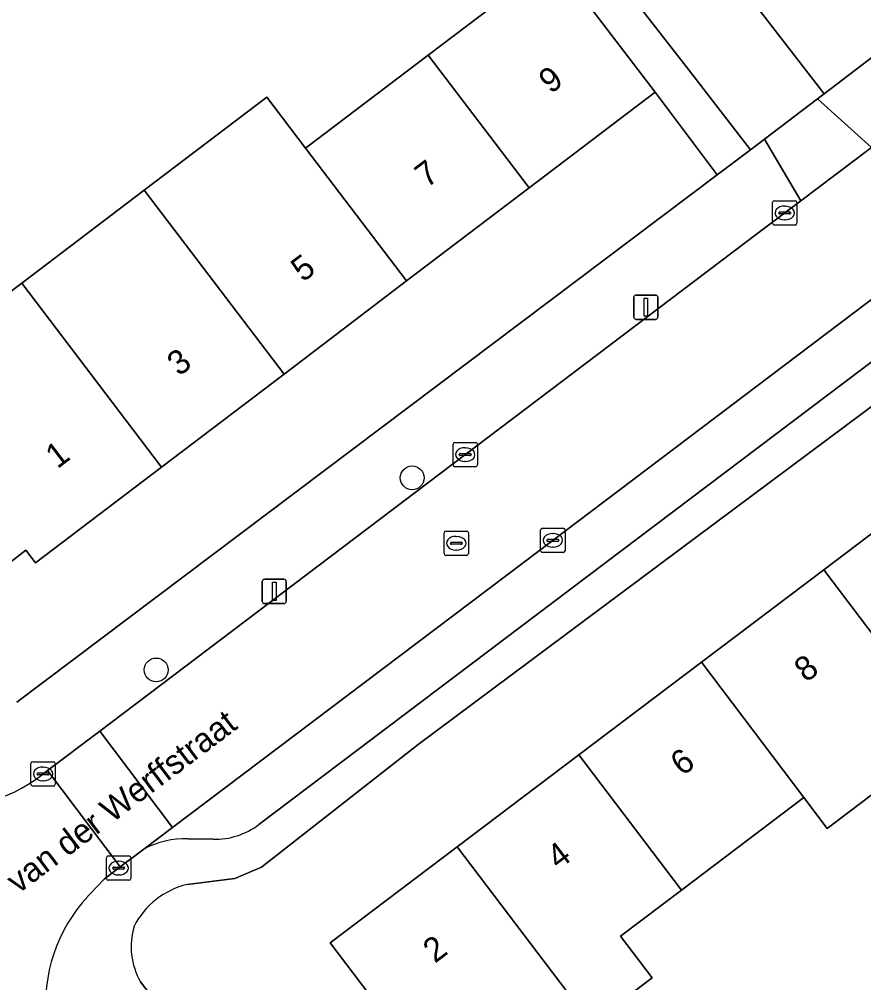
# Model space of a CAD drawing. Extents: x 160030 to 160839, y 385325 to 386450.
# Drawn here: x 160405.72 to 160440.44, y 385842.6 to 385882.22 of the extents above; entities that cross this region are included whole.
import ezdxf

# ---------------------------------------------------------------- set-up
doc = ezdxf.new("R2010")
doc.units = 0
for name, color, linetype in [('IMGEO_Boom', 7, 'Continuous'), ('IMGEO_Erf', 7, 'Continuous'), ('IMGEO_Kolk', 7, 'Continuous'), ('IMGEO_Lichtmast', 7, 'Continuous'), ('IMGEO_Openbare_ruimte_label', 7, 'Continuous'), ('IMGEO_Pand', 7, 'Continuous'), ('IMGEO_Pand_nummerreeks', 7, 'Continuous'), ('IMGEO_Parkeervlak_open', 7, 'Continuous'), ('IMGEO_Rijbaan_lokaal_open', 7, 'Continuous'), ('IMGEO_Rioolput', 7, 'Continuous'), ('IMGEO_Voetpad_open', 7, 'Continuous')]:
    doc.layers.add(name, color=color, linetype=linetype)

msp = doc.modelspace()

# ---------------------------------------------------------------- linework, layer by layer
at = {"layer": 'IMGEO_Boom'}
for centre in [(160421.874, 385863.359), (160411.348, 385855.461)]:
    msp.add_circle(centre, 0.489, dxfattribs=at)
at = {"layer": 'IMGEO_Erf'}
for points in [[(160420.415, 385933.281), (160423.895, 385928.01), (160427.375, 385922.74), (160430.855, 385917.469), (160434.335, 385912.199), (160437.816, 385906.927), (160441.295, 385901.657), (160444.694, 385896.509), (160444.776, 385896.386), (160446.359, 385893.988), (160447.234, 385894.566), (160447.346, 385894.286), (160449.936, 385890.337), (160446.568, 385888.118), (160445.867, 385889.187), (160441.475, 385886.287), (160439.601, 385889.125), (160434.092, 385885.242), (160436.233, 385882.478), (160438.808, 385879.155), (160450.853, 385888.364)], [(160415.895, 385879.021), (160417.494, 385876.916), (160422.532, 385880.746), (160427.708, 385884.68)], [(160405.621, 385854.135), (160434.418, 385875.821), (160431.858, 385879.22), (160426.682, 385875.285), (160421.644, 385871.456), (160416.605, 385867.626), (160411.568, 385863.797), (160406.392, 385859.863), (160405.996, 385860.384), (160404.814, 385859.485), (160403.13, 385861.701), (160404.306, 385862.595), (160402.235, 385865.319), (160400.625, 385867.441), (160405.82, 385871.362), (160410.857, 385875.191), (160415.895, 385879.021)], [(160438.794, 385859.583), (160443.827, 385863.39), (160449.02, 385867.319), (160450.696, 385865.104), (160452.838, 385866.725), (160448.695, 385872.214), (160446.573, 385870.631), (160422.124, 385852.4), (160415.683, 385847.347), (160414.577, 385846.885), (160412.621, 385846.639)], [(160410.71, 385842.631), (160424.459, 385824.597), (160430.089, 385828.889), (160428.548, 385830.926), (160426.66, 385833.421), (160428.183, 385834.573), (160424.807, 385839.037), (160422.223, 385837.082), (160419.315, 385840.926), (160420.391, 385841.74), (160418.504, 385844.234), (160423.728, 385848.186), (160428.73, 385851.97), (160433.762, 385855.777), (160438.794, 385859.583)], [(160443.965, 385852.747), (160438.934, 385848.941), (160437.974, 385850.21), (160432.942, 385846.403), (160430.444, 385844.513), (160431.738, 385842.801), (160429.235, 385840.908), (160431.9, 385837.385), (160432.944, 385836.044), (160437.184, 385839.347), (160439.577, 385836.275), (160442.546, 385838.653)]]:
    msp.add_lwpolyline(points, dxfattribs=at)
for centre, radius, start, end in [((160413.395, 385843.416), 3.315, 103.5014, 152.9338), ((160413.213, 385844.085), 2.895, 163.142, 210.1414)]:
    msp.add_arc(centre, radius, start, end, dxfattribs=at)
at = {"layer": 'IMGEO_Kolk'}
for p, q in [((160436.765, 385874.755), (160437.617, 385874.755)), ((160436.69, 385873.829), (160436.69, 385874.681)), ((160436.992, 385874.298), (160437.39, 385874.298)), ((160437.178, 385874.535), (160437.203, 385874.535)), ((160437.691, 385874.681), (160437.691, 385873.829)), ((160436.949, 385874.249), (160436.949, 385874.261)), ((160437.387, 385874.212), (160436.989, 385874.212)), ((160437.201, 385873.975), (160437.176, 385873.975)), ((160437.433, 385874.261), (160437.433, 385874.249)), ((160437.617, 385873.755), (160436.765, 385873.755)), ((160423.627, 385864.818), (160424.479, 385864.818)), ((160423.552, 385863.892), (160423.552, 385864.744)), ((160424.04, 385864.598), (160424.065, 385864.598)), ((160424.553, 385864.744), (160424.553, 385863.892)), ((160423.811, 385864.312), (160423.811, 385864.324)), ((160424.249, 385864.275), (160423.851, 385864.275)), ((160423.854, 385864.361), (160424.252, 385864.361)), ((160424.063, 385864.038), (160424.038, 385864.038)), ((160424.295, 385864.324), (160424.295, 385864.312)), ((160424.479, 385863.818), (160423.627, 385863.818)), ((160427.155, 385860.364), (160427.155, 385861.216)), ((160427.23, 385861.29), (160428.082, 385861.29)), ((160428.156, 385861.216), (160428.156, 385860.364)), ((160427.457, 385860.833), (160427.855, 385860.833)), ((160427.643, 385861.07), (160427.668, 385861.07)), ((160427.414, 385860.784), (160427.414, 385860.796)), ((160427.852, 385860.747), (160427.454, 385860.747)), ((160427.666, 385860.51), (160427.641, 385860.51)), ((160427.898, 385860.796), (160427.898, 385860.784)), ((160428.082, 385860.29), (160427.23, 385860.29)), ((160406.2, 385850.76), (160406.2, 385851.612)), ((160406.275, 385851.686), (160407.127, 385851.686)), ((160406.688, 385851.466), (160406.713, 385851.466)), ((160407.201, 385851.612), (160407.201, 385850.76)), ((160406.459, 385851.18), (160406.459, 385851.192)), ((160406.897, 385851.143), (160406.499, 385851.143)), ((160406.502, 385851.229), (160406.9, 385851.229)), ((160406.943, 385851.192), (160406.943, 385851.18)), ((160407.127, 385850.686), (160406.275, 385850.686)), ((160406.711, 385850.906), (160406.686, 385850.906)), ((160409.378, 385847.812), (160410.23, 385847.812)), ((160409.303, 385846.886), (160409.303, 385847.738)), ((160409.605, 385847.355), (160410.003, 385847.355)), ((160409.791, 385847.592), (160409.816, 385847.592)), ((160410.304, 385847.738), (160410.304, 385846.886)), ((160409.562, 385847.306), (160409.562, 385847.318)), ((160410, 385847.269), (160409.602, 385847.269)), ((160409.814, 385847.032), (160409.789, 385847.032)), ((160410.046, 385847.318), (160410.046, 385847.306)), ((160410.23, 385846.812), (160409.378, 385846.812))]:
    msp.add_line(p, q, dxfattribs=at)
for points in [[(160436.765, 385874.755), (160437.617, 385874.755)], [(160436.69, 385873.829), (160436.69, 385874.681)], [(160437.691, 385874.681), (160437.691, 385873.829)], [(160437.617, 385873.755), (160436.765, 385873.755)], [(160423.627, 385864.818), (160424.479, 385864.818)], [(160423.552, 385863.892), (160423.552, 385864.744)], [(160424.553, 385864.744), (160424.553, 385863.892)], [(160424.479, 385863.818), (160423.627, 385863.818)], [(160427.155, 385860.364), (160427.155, 385861.216)], [(160427.23, 385861.29), (160428.082, 385861.29)], [(160428.156, 385861.216), (160428.156, 385860.364)], [(160428.082, 385860.29), (160427.23, 385860.29)], [(160406.2, 385850.76), (160406.2, 385851.612)], [(160406.275, 385851.686), (160407.127, 385851.686)], [(160407.201, 385851.612), (160407.201, 385850.76)], [(160407.127, 385850.686), (160406.275, 385850.686)], [(160409.378, 385847.812), (160410.23, 385847.812)], [(160409.303, 385846.886), (160409.303, 385847.738)], [(160410.304, 385847.738), (160410.304, 385846.886)], [(160410.23, 385846.812), (160409.378, 385846.812)]]:
    msp.add_lwpolyline(points, dxfattribs=at)
for centre, radius, start, end in [((160436.767, 385874.679), 0.0765, 91.552, 178.448), ((160436.767, 385874.679), 0.0765, 91.552, 178.448), ((160437.615, 385874.679), 0.0765, 1.552, 88.448), ((160437.615, 385874.679), 0.0765, 1.552, 88.448), ((160436.989, 385874.258), 0.0403, 85.8775, 175.7526), ((160437.394, 385874.26), 0.0386, 1.7309, 96.639), ((160436.986, 385874.248), 0.0366, 178.938, 274.7102), ((160437.39, 385874.255), 0.043, 264.8664, 352.4533), ((160436.767, 385873.831), 0.0765, 181.552, 268.448), ((160436.767, 385873.831), 0.0765, 181.552, 268.448), ((160437.615, 385873.831), 0.0765, 271.552, 358.448), ((160437.615, 385873.831), 0.0765, 271.552, 358.448), ((160423.629, 385864.742), 0.0765, 91.552, 178.448), ((160423.629, 385864.742), 0.0765, 91.552, 178.448), ((160424.477, 385864.742), 0.0765, 1.552, 88.448), ((160424.477, 385864.742), 0.0765, 1.552, 88.448), ((160423.851, 385864.321), 0.0403, 85.8775, 175.7526), ((160423.848, 385864.311), 0.0366, 178.938, 274.7102), ((160424.252, 385864.318), 0.043, 264.8664, 352.4533), ((160424.256, 385864.323), 0.0386, 1.7309, 96.639), ((160423.629, 385863.894), 0.0765, 181.552, 268.448), ((160423.629, 385863.894), 0.0765, 181.552, 268.448), ((160424.477, 385863.894), 0.0765, 271.552, 358.448), ((160424.477, 385863.894), 0.0765, 271.552, 358.448), ((160427.232, 385861.214), 0.0765, 91.552, 178.448), ((160427.232, 385861.214), 0.0765, 91.552, 178.448), ((160428.08, 385861.214), 0.0765, 1.552, 88.448), ((160428.08, 385861.214), 0.0765, 1.552, 88.448), ((160427.454, 385860.793), 0.0403, 85.8775, 175.7526), ((160427.859, 385860.795), 0.0386, 1.7309, 96.639), ((160427.451, 385860.783), 0.0366, 178.938, 274.7102), ((160427.855, 385860.79), 0.043, 264.8664, 352.4533), ((160427.232, 385860.366), 0.0765, 181.552, 268.448), ((160427.232, 385860.366), 0.0765, 181.552, 268.448), ((160428.08, 385860.366), 0.0765, 271.552, 358.448), ((160428.08, 385860.366), 0.0765, 271.552, 358.448), ((160406.277, 385851.61), 0.0765, 91.552, 178.448), ((160406.277, 385851.61), 0.0765, 91.552, 178.448), ((160407.125, 385851.61), 0.0765, 1.552, 88.448), ((160407.125, 385851.61), 0.0765, 1.552, 88.448), ((160406.499, 385851.189), 0.0403, 85.8775, 175.7526), ((160406.496, 385851.179), 0.0366, 178.938, 274.7102), ((160406.9, 385851.186), 0.043, 264.8664, 352.4533), ((160406.904, 385851.191), 0.0386, 1.7309, 96.639), ((160406.277, 385850.762), 0.0765, 181.552, 268.448), ((160406.277, 385850.762), 0.0765, 181.552, 268.448), ((160407.125, 385850.762), 0.0765, 271.552, 358.448), ((160407.125, 385850.762), 0.0765, 271.552, 358.448), ((160409.38, 385847.736), 0.0765, 91.552, 178.448), ((160409.38, 385847.736), 0.0765, 91.552, 178.448), ((160410.228, 385847.736), 0.0765, 1.552, 88.448), ((160410.228, 385847.736), 0.0765, 1.552, 88.448), ((160409.602, 385847.315), 0.0403, 85.8775, 175.7526), ((160410.007, 385847.317), 0.0386, 1.7309, 96.639), ((160409.599, 385847.305), 0.0366, 178.938, 274.7102), ((160410.003, 385847.312), 0.043, 264.8664, 352.4533), ((160409.38, 385846.888), 0.0765, 181.552, 268.448), ((160409.38, 385846.888), 0.0765, 181.552, 268.448), ((160410.228, 385846.888), 0.0765, 271.552, 358.448), ((160410.228, 385846.888), 0.0765, 271.552, 358.448)]:
    msp.add_arc(centre, radius, start, end, dxfattribs=at)
for centre, major_axis, ratio, start_param, end_param in [((160437.177, 385874.255), (-0.387, 0.002), 0.722429, 4.712389, 7.853982), ((160437.202, 385874.255), (-0.39, 0.002), 0.717154, 1.570796, 4.712389), ((160424.039, 385864.318), (-0.387, 0.002), 0.722429, 4.712389, 7.853982), ((160424.064, 385864.318), (-0.39, 0.002), 0.717154, 1.570796, 4.712389), ((160427.642, 385860.79), (-0.387, 0.002), 0.722429, 4.712389, 7.853982), ((160427.667, 385860.79), (-0.39, 0.002), 0.717154, 1.570796, 4.712389), ((160406.687, 385851.186), (-0.387, 0.002), 0.722429, 4.712389, 7.853982), ((160406.712, 385851.186), (-0.39, 0.002), 0.717154, 1.570796, 4.712389), ((160409.79, 385847.312), (-0.387, 0.002), 0.722429, 4.712389, 7.853982), ((160409.815, 385847.312), (-0.39, 0.002), 0.717154, 1.570796, 4.712389)]:
    msp.add_ellipse(centre, major_axis=major_axis, ratio=ratio, start_param=start_param, end_param=end_param, dxfattribs=at)
at = {"layer": 'IMGEO_Lichtmast'}
for p, q in [((160430.984, 385869.978), (160430.984, 385870.778)), ((160430.984, 385870.778), (160430.984, 385869.978)), ((160431.084, 385870.878), (160431.874, 385870.878)), ((160431.874, 385870.878), (160431.084, 385870.878)), ((160431.974, 385870.778), (160431.974, 385869.978)), ((160431.974, 385869.978), (160431.974, 385870.778)), ((160431.874, 385869.878), (160431.084, 385869.878)), ((160431.084, 385869.878), (160431.874, 385869.878)), ((160415.705, 385858.292), (160415.705, 385859.092)), ((160415.705, 385859.092), (160415.705, 385858.292)), ((160415.805, 385859.192), (160416.595, 385859.192)), ((160416.595, 385859.192), (160415.805, 385859.192)), ((160416.695, 385859.092), (160416.695, 385858.292)), ((160416.695, 385858.292), (160416.695, 385859.092)), ((160416.595, 385858.192), (160415.805, 385858.192)), ((160415.805, 385858.192), (160416.595, 385858.192))]:
    msp.add_line(p, q, dxfattribs=at)
for points in [[(160431.404, 385870.753), (160431.554, 385870.753), (160431.554, 385870.003), (160431.404, 385870.003), (160431.404, 385870.753)], [(160416.125, 385859.067), (160416.275, 385859.067), (160416.275, 385858.317), (160416.125, 385858.317), (160416.125, 385859.067)]]:
    msp.add_lwpolyline(points, dxfattribs=at)
for centre, start, end in [((160431.084, 385870.778), 90, 180), ((160431.084, 385870.778), 90, 180), ((160431.874, 385870.778), 0, 90), ((160431.874, 385870.778), 360, 90), ((160431.084, 385869.978), 180, 270), ((160431.084, 385869.978), 180, 270), ((160431.874, 385869.978), 270, 0), ((160431.874, 385869.978), 270, 0), ((160415.805, 385859.092), 90, 180), ((160415.805, 385859.092), 90, 180), ((160416.595, 385859.092), 0, 90), ((160416.595, 385859.092), 360, 90), ((160415.805, 385858.292), 180, 270), ((160415.805, 385858.292), 180, 270), ((160416.595, 385858.292), 270, 0), ((160416.595, 385858.292), 270, 0)]:
    msp.add_arc(centre, 0.1, start, end, dxfattribs=at)
at = {"layer": 'IMGEO_Pand'}
for points in [[(160447.346, 385894.286), (160447.234, 385894.566), (160446.359, 385893.988), (160444.776, 385896.386), (160436.026, 385890.609), (160436.235, 385890.293), (160429.208, 385885.34), (160433.229, 385880.15), (160435.785, 385876.851), (160436.363, 385877.291), (160438.538, 385878.95), (160438.808, 385879.155), (160436.233, 385882.478), (160434.092, 385885.242), (160439.601, 385889.125), (160441.475, 385886.287), (160445.867, 385889.187), (160446.568, 385888.118), (160449.936, 385890.337)], [(160426.682, 385875.285), (160431.858, 385879.22), (160428.832, 385883.201), (160427.708, 385884.68), (160422.532, 385880.746)], [(160421.644, 385871.456), (160426.682, 385875.285), (160422.532, 385880.746), (160417.494, 385876.916)], [(160415.895, 385879.021), (160410.857, 385875.191), (160416.605, 385867.626), (160421.644, 385871.456), (160417.494, 385876.916)], [(160405.82, 385871.362), (160411.568, 385863.797), (160416.605, 385867.626), (160410.857, 385875.191)], [(160404.306, 385862.595), (160403.13, 385861.701), (160404.814, 385859.485), (160405.996, 385860.384), (160406.392, 385859.863), (160411.568, 385863.797), (160405.82, 385871.362), (160400.625, 385867.441), (160402.235, 385865.319)], [(160443.965, 385852.747), (160448.998, 385856.554), (160443.827, 385863.39), (160438.794, 385859.583)], [(160438.794, 385859.583), (160433.762, 385855.777), (160437.974, 385850.21), (160438.934, 385848.941), (160443.965, 385852.747)], [(160432.942, 385846.403), (160437.974, 385850.21), (160433.762, 385855.777), (160428.73, 385851.97)], [(160428.73, 385851.97), (160423.728, 385848.186), (160427.94, 385842.619), (160429.235, 385840.908), (160431.738, 385842.801), (160430.444, 385844.513), (160432.942, 385846.403)], [(160423.728, 385848.186), (160418.504, 385844.234), (160420.391, 385841.74), (160419.315, 385840.926), (160422.223, 385837.082), (160424.807, 385839.037), (160428.183, 385834.573), (160431.9, 385837.385), (160429.235, 385840.908), (160427.94, 385842.619)]]:
    msp.add_lwpolyline(points, close=True, dxfattribs=at)
at = {"layer": 'IMGEO_Parkeervlak_open'}
for points in [[(160447.076, 385875.542), (160443.404, 385872.69), (160426.43, 385859.865), (160412.023, 385848.989), (160410.839, 385848.095)], [(160415.566, 385849.104), (160427.661, 385858.235), (160444.594, 385871.028)], [(160412.663, 385848.523), (160413.69, 385848.499)]]:
    msp.add_lwpolyline(points, dxfattribs=at)
for centre, radius, start, end in [((160413.758, 385851.498), 3, 268.6962, 307.0523), ((160412.597, 385844.705), 3.818, 89.0031, 117.4079)]:
    msp.add_arc(centre, radius, start, end, dxfattribs=at)
at = {"layer": 'IMGEO_Rijbaan_lokaal_open'}
for points in [[(160443.404, 385872.69), (160447.076, 385875.542), (160449.202, 385877.266), (160452.197, 385879.558), (160453.06, 385880.219), (160450.2, 385884.038), (160440.762, 385876.939), (160437.848, 385874.748), (160436.031, 385873.381), (160409.033, 385852.95), (160412.023, 385848.989), (160426.43, 385859.865)], [(160409.868, 385847.362), (160410.839, 385848.095), (160412.023, 385848.989), (160409.033, 385852.95), (160406.88, 385851.321)]]:
    msp.add_lwpolyline(points, close=True, dxfattribs=at)
msp.add_lwpolyline([(160408.532, 385846.148), (160408.633, 385846.261), (160409.205, 385846.861), (160409.868, 385847.362), (160406.88, 385851.321), (160406.582, 385851.095)], dxfattribs=at)
for centre, radius, start, end in [((160402.795, 385856.104), 6.279, 262.3776, 307.0912), ((160413.391, 385841.69), 6.594, 137.4643, 185.4835)]:
    msp.add_arc(centre, radius, start, end, dxfattribs=at)
at = {"layer": 'IMGEO_Rioolput'}
for p, q in [((160423.184, 385860.246), (160423.184, 385861.098)), ((160423.259, 385861.172), (160424.111, 385861.172)), ((160423.672, 385860.952), (160423.697, 385860.952)), ((160424.185, 385861.098), (160424.185, 385860.246)), ((160423.443, 385860.666), (160423.443, 385860.678)), ((160423.881, 385860.629), (160423.483, 385860.629)), ((160423.486, 385860.715), (160423.884, 385860.715)), ((160423.927, 385860.678), (160423.927, 385860.666)), ((160424.111, 385860.172), (160423.259, 385860.172)), ((160423.695, 385860.392), (160423.67, 385860.392))]:
    msp.add_line(p, q, dxfattribs=at)
for points in [[(160423.184, 385860.246), (160423.184, 385861.098)], [(160423.259, 385861.172), (160424.111, 385861.172)], [(160424.185, 385861.098), (160424.185, 385860.246)], [(160424.111, 385860.172), (160423.259, 385860.172)]]:
    msp.add_lwpolyline(points, dxfattribs=at)
for centre, radius, start, end in [((160423.261, 385861.096), 0.0765, 91.552, 178.448), ((160423.261, 385861.096), 0.0765, 91.552, 178.448), ((160424.109, 385861.096), 0.0765, 1.552, 88.448), ((160424.109, 385861.096), 0.0765, 1.552, 88.448), ((160423.483, 385860.675), 0.0403, 85.8775, 175.7526), ((160423.48, 385860.665), 0.0366, 178.938, 274.7102), ((160423.884, 385860.672), 0.043, 264.8664, 352.4533), ((160423.888, 385860.677), 0.0386, 1.7309, 96.639), ((160423.261, 385860.248), 0.0765, 181.552, 268.448), ((160423.261, 385860.248), 0.0765, 181.552, 268.448), ((160424.109, 385860.248), 0.0765, 271.552, 358.448), ((160424.109, 385860.248), 0.0765, 271.552, 358.448)]:
    msp.add_arc(centre, radius, start, end, dxfattribs=at)
for centre, major_axis, ratio, start_param, end_param in [((160423.671, 385860.672), (-0.387, 0.002), 0.722429, 4.712389, 7.853982), ((160423.696, 385860.672), (-0.39, 0.002), 0.717154, 1.570796, 4.712389)]:
    msp.add_ellipse(centre, major_axis=major_axis, ratio=ratio, start_param=start_param, end_param=end_param, dxfattribs=at)
at = {"layer": 'IMGEO_Voetpad_open'}
for points in [[(160450.853, 385888.364), (160438.808, 385879.155), (160438.538, 385878.95), (160440.762, 385876.939), (160450.2, 385884.038), (160450.387, 385884.179), (160452.524, 385885.786), (160452.649, 385885.88), (160453.978, 385886.975)], [(160428.832, 385883.201), (160431.858, 385879.22), (160434.418, 385875.821), (160435.785, 385876.851), (160433.229, 385880.15), (160429.208, 385885.34)], [(160436.031, 385873.381), (160437.848, 385874.748), (160436.363, 385877.291), (160435.785, 385876.851), (160434.418, 385875.821), (160405.621, 385854.135)], [(160406.582, 385851.095), (160406.88, 385851.321), (160409.033, 385852.95), (160436.031, 385873.381)], [(160412.621, 385846.639), (160414.577, 385846.885), (160415.683, 385847.347), (160422.124, 385852.4), (160446.573, 385870.631), (160445.654, 385871.862), (160445.539, 385871.977), (160444.594, 385871.028), (160427.661, 385858.235), (160415.566, 385849.104)], [(160413.69, 385848.499), (160412.663, 385848.523)], [(160410.839, 385848.095), (160409.868, 385847.362), (160409.205, 385846.861), (160408.633, 385846.261), (160408.532, 385846.148)], [(160425.422, 385823.334), (160424.459, 385824.597), (160410.71, 385842.631)]]:
    msp.add_lwpolyline(points, dxfattribs=at)
msp.add_lwpolyline([(160436.363, 385877.291), (160437.848, 385874.748), (160440.762, 385876.939), (160438.538, 385878.95)], close=True, dxfattribs=at)
for centre, radius, start, end in [((160402.795, 385856.104), 6.279, 262.3776, 307.0912), ((160413.758, 385851.498), 3, 268.6962, 307.0523), ((160412.597, 385844.705), 3.818, 89.0031, 117.4079), ((160413.395, 385843.416), 3.315, 103.5014, 152.9338), ((160413.391, 385841.69), 6.594, 137.4643, 185.4835), ((160413.213, 385844.085), 2.895, 163.142, 210.1414)]:
    msp.add_arc(centre, radius, start, end, dxfattribs=at)

# ---------------------------------------------------------------- texts
at = {"layer": 'IMGEO_Openbare_ruimte_label'}
msp.add_text('van der Werffstraat', height=1, rotation=37.0761, dxfattribs=at).set_placement((160405.677, 385846.232))
at = {"layer": 'IMGEO_Pand_nummerreeks'}
for s, rotation, p in [('9', 37.2389, (160427.567, 385879.124)), ('7', 37.2389, (160422.474, 385875.253)), ('5', 37.2389, (160417.381, 385871.381)), ('3', 37.2389, (160412.288, 385867.51)), ('1', 37.2389, (160407.286, 385863.707)), ('8', 37.1071, (160438.067, 385854.921)), ('6', 37.1071, (160432.978, 385851.071)), ('4', 37.1071, (160427.892, 385847.223)), ('2', 37.1047, (160422.806, 385843.375))]:
    msp.add_text(s, height=1, rotation=rotation, dxfattribs=at).set_placement(p)

doc.saveas('drawing.dxf')
